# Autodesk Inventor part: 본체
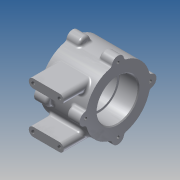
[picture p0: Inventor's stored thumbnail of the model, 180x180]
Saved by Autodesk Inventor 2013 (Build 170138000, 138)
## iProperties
Created: 2015-03
Part Number: 본체
Material: 알루미늄 6061
Document SubType Name: Modeling
Designer: kb543
Density: 2.71 g/cm^3
Mass: 451.224 g
Surface Area: 335.777 cm^2
Volume: 166.503 cm^3
Author: kb543
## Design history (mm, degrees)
sketch "스케치1"
  geometry: L1 (-40, 0)-(40, 0); L2 (-26, 0)-(-26, 37); L3 (-26, 37)-(26, 37); L4 (26, 37)-(26, 0); L5 (-26, 23.5)-(-4, 23.5); L6 (-4, 23.5)-(-4, 21); L7 (-4, 21)-(4, 21); L8 (4, 21)-(4, 23.5); L9 (4, 23.5)-(26, 23.5); 4 further points
  constraints: 18 end point, 6 perpendicular, 4 point on line, 3 midpoint, 2 parallel, 2 vertical alignment, 1 coincident, 1 horizontal
  dimensions: "d0" = 80 distance of L1.start L1.end; "d2" = 74 diameter of L3 L1; "d3" = 52 distance of L2.end L3.end; "d4" = 22 distance of L5.start L5.end; "d5" = 47 diameter of L5 L1; "d6" = 47 diameter of L9 L1; "d7" = 42 diameter of L7 L1
revolve "회전1" sketch "스케치1" stored, may be unused: angle "d8" = 90 deg
sketch "스케치2"
  geometry: C1 r 7 at (0, 37); 2 further points
  constraints: 1 centre point, 1 coincident, 1 vertical alignment, 1 other
  dimensions: "d9" = 7 radius of C1
extrude "돌출1" join sketch "스케치2" distance "d11" = 15; taper "d12" = 0 deg
hole "구멍1" sketch "스케치2" diameter "d13" = 3.242; stored, may be unused: countersink angle "d17" = 90 deg, drill point angle "d19" = 118 deg; dims "d14" = 8, "d15" = 4, "d16" = 2, "d18" = 11
node "작업 평면2"
sketch "스케치3"
  geometry: L1 (15, 19)-(-15, 19); L2 (-15, 19)-(-15, 29); L3 (-15, 29)-(15, 29); L4 (15, 29)-(15, 19); L5 (-36.4, 0)-(36.4, 0) reference; L6 (15, -19)-(-15, -19); L7 (-15, -19)-(-15, -29); L8 (-15, -29)-(15, -29); L9 (15, -29)-(15, -19); A1 r 5 centre (15, 24) between (15, 19) and (15, 29); A2 r 5 centre (-15, 24) between (-15, 29) and (-15, 19); A3 r 5 centre (15, -24) between (15, -29) and (15, -19); A4 r 5 centre (-15, -24) between (-15, -19) and (-15, -29); 3 further points
  constraints: 16 end point, 8 point on circle, 7 symmetric about line, 4 centre point, 3 midpoint, 2 parallel, 1 horizontal, 1 perpendicular, 1 vertical alignment, 2 other
  dimensions: "d25" = 10 distance of L3.end L1.start; "d31" = 30 distance between parallel lines of L2 L4; "d32" = 48 distance of A2.centre A4.centre
extrude "돌출2" join sketch "스케치3" stored distance "d33" = 10; taper "d34" = 0 deg
sketch "스케치4"
  geometry: A1 r 5 centre (15, -24) between (15, -29) and (15, -19) reference; A2 r 5 centre (-15, -24) between (-15, -19) and (-15, -29) reference; A3 r 5 centre (15, 24) between (15, 19) and (15, 29) reference; A4 r 5 centre (-15, 24) between (-15, 29) and (-15, 19) reference; 5 further points
  constraints: 4 coincident
hole "구멍2" sketch "스케치4" at (-15, 24), (15, 24), (15, -24), (-15, -24) diameter "d35" = 4.134; stored, may be unused: countersink angle "d39" = 90 deg, drill point angle "d41" = 118 deg; dims "d36" = 6, "d37" = 4, "d38" = 2, "d40" = 8
node "작업 평면6"
  node "작업 평면5"
sketch "스케치5"
  geometry: L1 (-26, 20.767)-(-26, -20.767) reference; L2 (0, -103.994)-(0, 89.929) reference; 3 further points
  constraints: 2 coincident, 1 vertical alignment, 1 other
  dimensions: "d52" = 26 distance from line of L1 point (0, 0) (derived)
feature "엠보싱1" sketch "스케치5" dims "d0" = 80, "d2" = 74, "d3" = 52, "d4" = 22, "d5" = 47, "d6" = 47, "d7" = 42, "d45" = 1, "d46" = 0
fillet "모깎기1" dims "d47" = 0.3
fillet "모깎기2" dims "d48" = 3
fillet "모깎기3" dims "d49" = 3
fillet "모깎기4" dims "d50" = 3
fillet "모깎기5" dims "d51" = 3
chamfer "모따기1" distance "d53" = 1; stored, may be unused: second distance "d54" = 2, angle "d55" = 45 deg
node "솔리드1"
pattern_circular "원형 패턴1" dims angle "d21" = 360 deg
mirror "대칭1"
node "작업 평면3"
other parameters: "d24" = -56, "d42" = -45 deg, "d44" = 0.5
